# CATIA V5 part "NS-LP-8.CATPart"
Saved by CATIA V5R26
Part number: NS-LP-8
Bounding box of the stored display mesh (mm): x -4.999 to 60, y -42 to 8, z -5 to 5
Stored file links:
  Y:\業務部\坪井宗男\KHI\KHI治工具標準部品\Lピン\CATIAデータ\NS-LP-8.CATPart
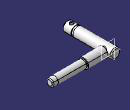
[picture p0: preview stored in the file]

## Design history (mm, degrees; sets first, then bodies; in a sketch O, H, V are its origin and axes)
Body1 (main body)
  Solid1: solid without history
